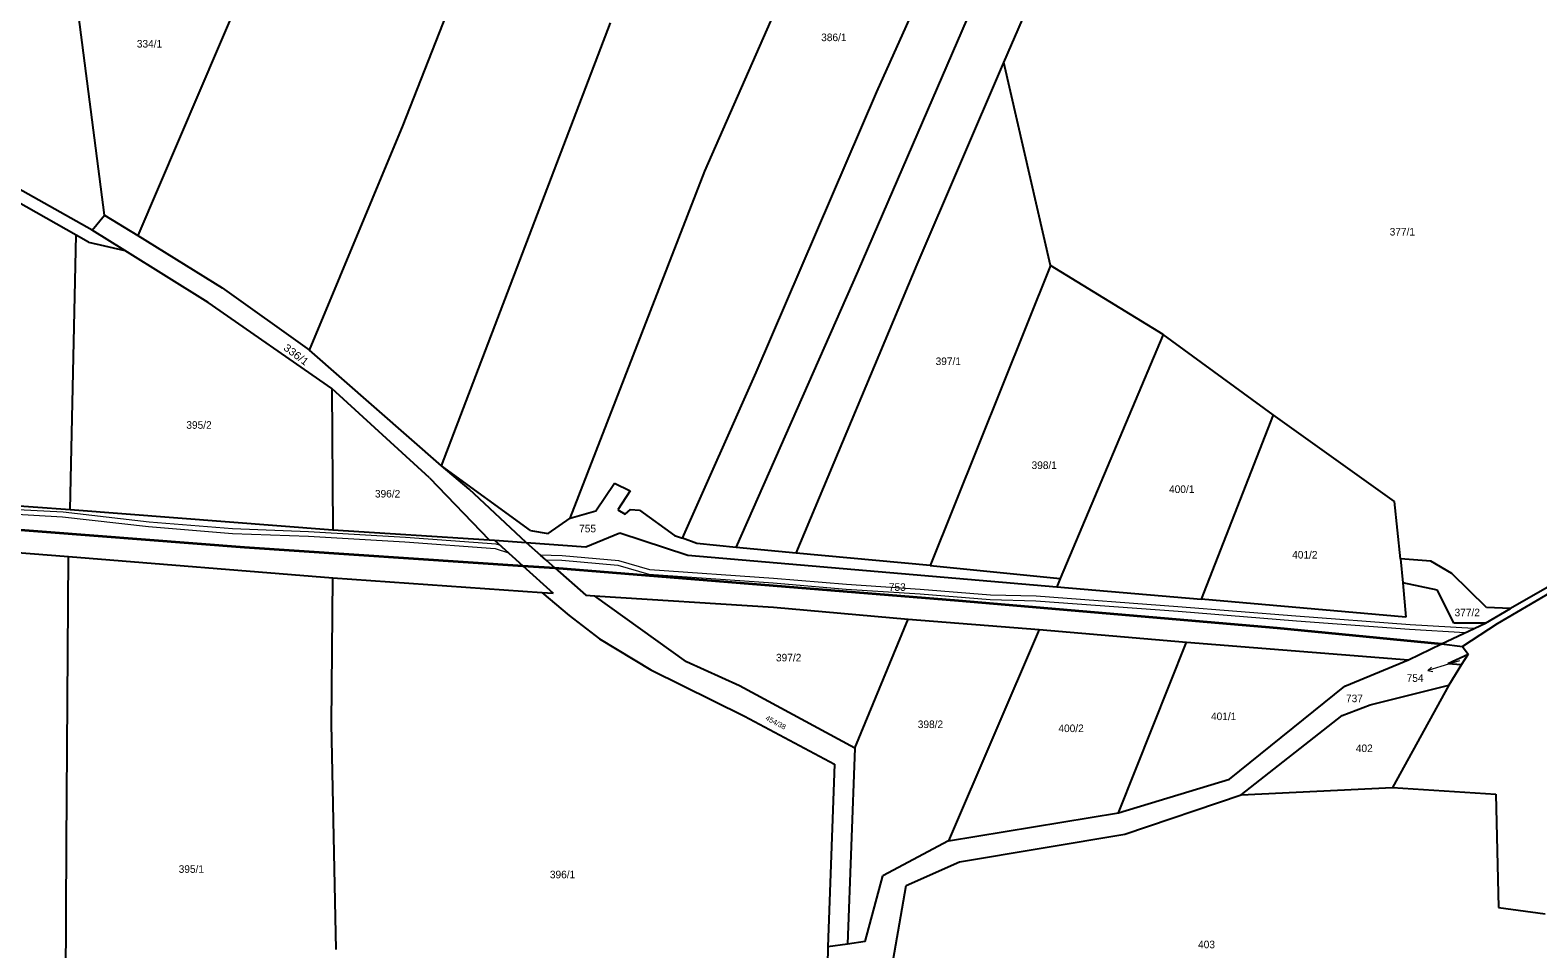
# Model space of a CAD drawing. Extents: x -701211 to -698780, y -1014269 to -1012378.
# Drawn here: x -699399.1 to -699060.5, y -1013138.2 to -1012931.8 of the extents above; entities that cross this region are included whole.
import ezdxf
from ezdxf.enums import TextEntityAlignment as Align

# ---------------------------------------------------------------- set-up
doc = ezdxf.new("R2010")
doc.units = 0
doc.header["$LTSCALE"] = 0.68
for name, color, linetype, lineweight in [('1', 7, 'Continuous', 25), ('13', 7, 'Continuous', 13), ('6', 7, 'Continuous', 35), ('7', 7, 'Continuous', 13)]:
    doc.layers.add(name, color=color, linetype=linetype, lineweight=lineweight)
doc.layers.add('2', color=7, linetype='Continuous')

msp = doc.modelspace()

# ---------------------------------------------------------------- linework, layer by layer
at = {"layer": '1'}
for p, q in [((-699315.38, -1012953.18), (-699282.37, -1012869.31)), ((-699213.15, -1012985.94), (-699171.72, -1012890.07)), ((-699247.57, -1012963.48), (-699219.57, -1012899.71)), ((-699208.92, -1012945.72), (-699188.64, -1012900.28)), ((-699343.08, -1012903.34), (-699374.97, -1012977.99)), ((-699382.43, -1012973.43), (-699389.21, -1012921.3)), ((-699306.73, -1013029.73), (-699268.81, -1012930.19)), ((-699180.4, -1012939.11), (-699176.26, -1012929.46)), ((-699199.86, -1012984.5), (-699180.4, -1012939.11)), ((-699169.92, -1012984.72), (-699180.4, -1012939.11)), ((-699236.04, -1013008.76), (-699208.92, -1012945.72)), ((-699336.38, -1013003.72), (-699315.38, -1012953.18)), ((-699385.19, -1012976.78), (-699423.42, -1012955.33)), ((-699388.78, -1012977.9), (-699423.33, -1012958.29)), ((-699277.87, -1013041.46), (-699247.57, -1012963.48)), ((-699385.19, -1012976.78), (-699382.43, -1012973.43)), ((-699382.43, -1012973.43), (-699374.97, -1012977.99)), ((-699377.88, -1012981.35), (-699385.19, -1012976.78)), ((-699390.16, -1013039.55), (-699388.78, -1012977.9)), ((-699386, -1012979.48), (-699388.78, -1012977.9)), ((-699386, -1012979.48), (-699377.88, -1012981.35)), ((-699374.97, -1012977.99), (-699356.03, -1012989.71)), ((-699359.17, -1012993.03), (-699377.88, -1012981.35)), ((-699227.06, -1013049.34), (-699199.86, -1012984.5)), ((-699240.53, -1013048.09), (-699213.15, -1012985.94)), ((-699169.92, -1012984.72), (-699196.99, -1013052.13)), ((-699144.6, -1013000.17), (-699169.92, -1012984.72)), ((-699356.03, -1012989.71), (-699336.38, -1013003.72)), ((-699331.35, -1013012.33), (-699359.17, -1012993.03)), ((-699144.6, -1013000.17), (-699167.76, -1013055)), ((-699119.96, -1013018.26), (-699144.6, -1013000.17)), ((-699306.73, -1013029.73), (-699336.38, -1013003.72)), ((-699252.6, -1013045.99), (-699236.04, -1013008.76)), ((-699309.45, -1013032.43), (-699331.35, -1013012.33)), ((-699331.35, -1013012.33), (-699331.18, -1013044.08)), ((-699119.96, -1013018.26), (-699136.09, -1013059.65)), ((-699092.66, -1013037.75), (-699119.96, -1013018.26)), ((-699300.53, -1013034.92), (-699306.73, -1013029.73)), ((-699286.75, -1013044.25), (-699306.73, -1013029.73)), ((-699446.49, -1013035.27), (-699390.16, -1013039.55)), ((-699309.45, -1013032.43), (-699296, -1013046.33)), ((-699287.76, -1013046.94), (-699300.53, -1013034.92)), ((-699272.08, -1013039.79), (-699267.86, -1013033.6)), ((-699267.86, -1013033.6), (-699264.36, -1013035.3)), ((-699264.36, -1013035.3), (-699267.14, -1013039.61)), ((-699091.32, -1013050.59), (-699092.66, -1013037.75)), ((-699390.16, -1013039.55), (-699331.18, -1013044.08)), ((-699282.81, -1013044.88), (-699277.87, -1013041.46)), ((-699277.87, -1013041.46), (-699272.08, -1013039.79)), ((-699267.14, -1013039.61), (-699265.52, -1013040.6)), ((-699265.52, -1013040.6), (-699264.27, -1013039.52)), ((-699264.27, -1013039.52), (-699262.29, -1013039.7)), ((-699262.29, -1013039.7), (-699254.39, -1013045.36)), ((-699331.18, -1013044.08), (-699296, -1013046.33)), ((-699286.75, -1013044.25), (-699282.81, -1013044.88)), ((-699274.3, -1013047.89), (-699266.67, -1013044.75)), ((-699266.67, -1013044.75), (-699251.38, -1013049.79)), ((-699254.39, -1013045.36), (-699252.6, -1013045.99)), ((-699446.4, -1013045.78), (-699390.54, -1013050.06)), ((-699296, -1013046.33), (-699294.85, -1013046.4)), ((-699294.85, -1013046.4), (-699288.48, -1013052.14)), ((-699294.85, -1013046.4), (-699287.76, -1013046.94)), ((-699287.76, -1013046.94), (-699274.3, -1013047.89)), ((-699287.76, -1013046.94), (-699281.32, -1013052.62)), ((-699249.42, -1013047.19), (-699252.6, -1013045.99)), ((-699240.53, -1013048.09), (-699249.42, -1013047.19)), ((-699227.06, -1013049.34), (-699240.53, -1013048.09)), ((-699391, -1013114.69), (-699390.54, -1013050.06)), ((-699390.54, -1013050.06), (-699331.15, -1013054.85)), ((-699288.48, -1013052.14), (-699281.65, -1013058.3)), ((-699251.38, -1013049.79), (-699168.54, -1013056.87)), ((-699196.99, -1013052.13), (-699227.06, -1013049.34)), ((-699196.99, -1013052.13), (-699167.76, -1013055)), ((-699091.32, -1013050.59), (-699090.82, -1013056.03)), ((-699084.49, -1013051.13), (-699091.32, -1013050.59)), ((-699079.82, -1013053.92), (-699084.49, -1013051.13)), ((-699331.48, -1013087.64), (-699331.15, -1013054.85)), ((-699331.15, -1013054.85), (-699284.19, -1013058.14)), ((-699281.32, -1013052.62), (-699274.34, -1013058.77)), ((-699167.76, -1013055), (-699168.54, -1013056.87)), ((-699072.01, -1013061.55), (-699079.82, -1013053.92)), ((-699053.15, -1013054.02), (-699066.63, -1013061.73)), ((-699284.19, -1013058.14), (-699281.65, -1013058.3)), ((-699284.19, -1013058.14), (-699278.04, -1013063.35)), ((-699274.34, -1013058.77), (-699272.4, -1013058.89)), ((-699272.4, -1013058.89), (-699232.15, -1013061.45)), ((-699251.72, -1013073.73), (-699272.4, -1013058.89)), ((-699168.54, -1013056.87), (-699136.09, -1013059.65)), ((-699083.01, -1013057.63), (-699090.82, -1013056.03)), ((-699090.82, -1013056.03), (-699090.15, -1013063.68)), ((-699079.31, -1013065.02), (-699083.01, -1013057.63)), ((-699054.42, -1013056.33), (-699069.61, -1013065.19)), ((-699232.15, -1013061.45), (-699201.91, -1013064.14)), ((-699090.15, -1013063.68), (-699136.09, -1013059.65)), ((-699072.25, -1013065.02), (-699066.63, -1013061.73)), ((-699066.63, -1013061.73), (-699072.01, -1013061.55)), ((-699278.04, -1013063.35), (-699271.22, -1013068.6)), ((-699213.87, -1013093.15), (-699201.91, -1013064.14)), ((-699201.91, -1013064.14), (-699172.51, -1013066.49)), ((-699082.15, -1013069.73), (-699072.25, -1013065.02)), ((-699072.25, -1013065.02), (-699079.31, -1013065.02)), ((-699069.61, -1013065.19), (-699077.38, -1013070.3)), ((-699271.22, -1013068.6), (-699259.75, -1013075.54)), ((-699172.51, -1013066.49), (-699192.82, -1013113.92)), ((-699172.51, -1013066.49), (-699139.41, -1013069.35)), ((-699154.69, -1013107.64), (-699139.41, -1013069.35)), ((-699139.41, -1013069.35), (-699089.56, -1013073.26)), ((-699089.56, -1013073.26), (-699082.15, -1013069.73)), ((-699082.15, -1013069.73), (-699077.38, -1013070.3)), ((-699080.67, -1013074.15), (-699076.16, -1013072.03)), ((-699077.38, -1013070.3), (-699076.16, -1013072.03)), ((-699076.16, -1013072.03), (-699076.94, -1013073.3)), ((-699259.75, -1013075.54), (-699238.66, -1013085.95)), ((-699239.83, -1013079.16), (-699251.72, -1013073.73)), ((-699103.81, -1013079.19), (-699089.56, -1013073.26)), ((-699080.67, -1013074.15), (-699077.61, -1013074.37)), ((-699077.61, -1013074.37), (-699080.49, -1013079.01)), ((-699076.94, -1013073.3), (-699077.61, -1013074.37)), ((-699213.87, -1013093.15), (-699239.83, -1013079.16)), ((-699129.74, -1013100.1), (-699103.81, -1013079.19)), ((-699098.16, -1013083.41), (-699080.49, -1013079.01)), ((-699080.49, -1013079.01), (-699093.09, -1013102)), ((-699238.66, -1013085.95), (-699218.5, -1013096.74)), ((-699127.14, -1013103.6), (-699104.44, -1013085.83)), ((-699104.44, -1013085.83), (-699098.16, -1013083.41)), ((-699330.4, -1013138.34), (-699331.48, -1013087.64)), ((-699213.87, -1013093.15), (-699215.58, -1013137.14)), ((-699218.5, -1013096.74), (-699219.95, -1013137.75)), ((-699154.69, -1013107.64), (-699129.74, -1013100.1)), ((-699127.14, -1013103.6), (-699093.09, -1013102)), ((-699093.09, -1013102), (-699069.93, -1013103.46)), ((-699153.25, -1013112.49), (-699127.14, -1013103.6)), ((-699069.93, -1013103.46), (-699069.35, -1013128.95)), ((-699192.82, -1013113.92), (-699154.69, -1013107.64)), ((-699190.4, -1013118.68), (-699153.25, -1013112.49)), ((-699391.31, -1013188.41), (-699391, -1013114.69)), ((-699192.82, -1013113.92), (-699207.57, -1013121.81)), ((-699202.33, -1013123.99), (-699190.4, -1013118.68)), ((-699211.56, -1013136.57), (-699207.57, -1013121.81)), ((-699208.97, -1013161.85), (-699202.33, -1013123.99)), ((-699069.35, -1013128.95), (-699058.85, -1013130.36)), ((-699211.56, -1013136.57), (-699215.58, -1013137.14)), ((-699219.95, -1013137.75), (-699220.32, -1013156.7)), ((-699215.58, -1013137.14), (-699219.95, -1013137.75))]:
    msp.add_line(p, q, dxfattribs=at)
at = {"layer": '13'}
msp.add_lwpolyline([(-699404.75, -1013040.45), (-699391.84, -1013041.13), (-699372.59, -1013043.37), (-699353.71, -1013044.9), (-699336.58, -1013045.54), (-699314.96, -1013046.77), (-699294.65, -1013048.3), (-699291.72, -1013049.22), (-699293.51, -1013047.61), (-699294.46, -1013047.31), (-699314.83, -1013045.78), (-699336.58, -1013044.54), (-699353.69, -1013043.9), (-699372.44, -1013042.38), (-699391.73, -1013040.13), (-699404.79, -1013039.45)], dxfattribs=at)
msp.add_lwpolyline([(-699283.38, -1013050.81), (-699279.72, -1013050.92), (-699267.11, -1013052.02), (-699260.14, -1013054.05), (-699232.22, -1013055.99), (-699215.82, -1013057.39), (-699199.22, -1013058.48), (-699183.48, -1013059.74), (-699173.23, -1013060.02), (-699141.24, -1013062.37), (-699114.66, -1013064.53), (-699089.28, -1013066.42), (-699076.8, -1013067.18), (-699074.93, -1013066.29), (-699089.16, -1013065.43), (-699114.81, -1013063.52), (-699141.37, -1013061.36), (-699173.18, -1013059.02), (-699183.45, -1013058.74), (-699199.21, -1013057.48), (-699215.77, -1013056.4), (-699232.19, -1013054.99), (-699259.97, -1013053.06), (-699266.92, -1013051.04), (-699279.67, -1013049.92), (-699284.56, -1013049.76)], close=True, dxfattribs=at)
at = {"layer": '6'}
for p, q in [((-699436.1, -1013041.4), (-699351.01, -1013047.96)), ((-699351.01, -1013047.96), (-699288.48, -1013052.14)), ((-699288.48, -1013052.14), (-699281.32, -1013052.62)), ((-699281.32, -1013052.62), (-699190.62, -1013059.98)), ((-699190.62, -1013059.98), (-699119.02, -1013066.07)), ((-699119.02, -1013066.07), (-699082.15, -1013069.73))]:
    msp.add_line(p, q, dxfattribs=at)
at = {"layer": '7'}
msp.add_line((-699085.15, -1013075.697), (-699084.046, -1013075.883), dxfattribs=at)
msp.add_lwpolyline([(-699078.06, -1013073.55), (-699082.28, -1013074.82), (-699085.15, -1013075.697), (-699084.339, -1013074.926)], dxfattribs=at)

# ---------------------------------------------------------------- texts
at = {"layer": '2'}
for s, p in [('386/1', (-699218.61, -1012934.295)), ('334/1', (-699372.33, -1012935.735)), ('377/1', (-699090.91, -1012977.965)), ('397/1', (-699192.9, -1013007.065)), ('395/2', (-699361.21, -1013021.385)), ('398/1', (-699171.35, -1013030.415)), ('396/2', (-699318.85, -1013036.825)), ('400/1', (-699140.47, -1013035.805)), ('755', (-699273.929, -1013044.645)), ('401/2', (-699112.82, -1013050.535)), ('377/2', (-699076.33, -1013063.505)), ('397/2', (-699228.76, -1013073.645)), ('737', (-699101.669, -1013082.805)), ('401/1', (-699131.05, -1013086.835)), ('398/2', (-699196.91, -1013088.625)), ('400/2', (-699165.32, -1013089.525)), ('402', (-699099.459, -1013094.015)), ('395/1', (-699362.93, -1013121.145)), ('396/1', (-699279.55, -1013122.375)), ('403', (-699134.899, -1013138.085))]:
    msp.add_text(s, height=1.7, dxfattribs=at).set_placement(p, align=Align.CENTER)
for s, height, rotation, width, p in [('336/1', 1.7, 323, 1.1, (-699339.8945, -1013005.3951)), ('454/38', 1.14, 332, 1.05, (-699231.9176, -1013087.8636))]:
    msp.add_text(s, height=height, rotation=rotation, dxfattribs=dict(at, width=width)).set_placement(p, align=Align.CENTER)
msp.add_text('753', height=1.7, dxfattribs=at).set_placement((-699206.25, -1013057.795))
msp.add_text('754', height=1.7, dxfattribs=at).set_placement((-699086.149, -1013078.245), align=Align.RIGHT)

doc.saveas('drawing.dxf')
